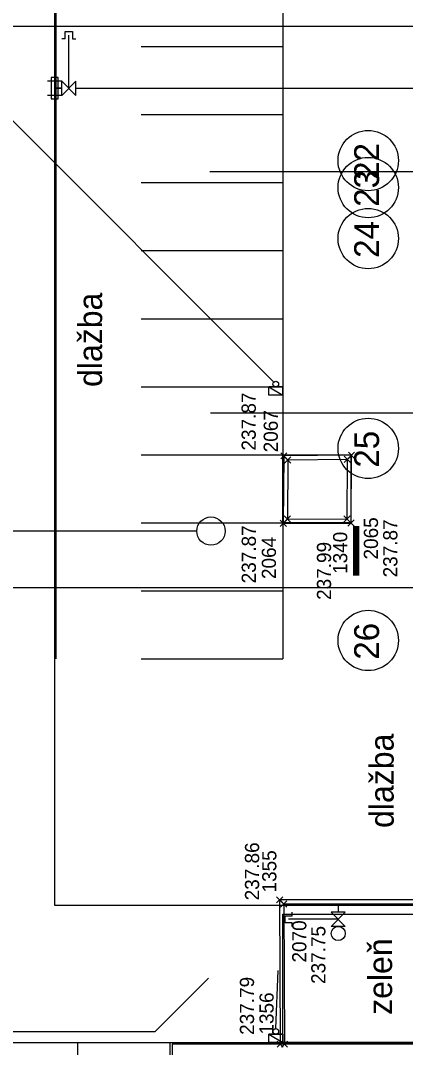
# Model space of a CAD drawing. Extents: x -264205 to -263659, y -1242401 to -1241986.
# Drawn here: x -263925.35 to -263911.77, y -1242255.16 to -1242218.94 of the extents above; entities that cross this region are included whole.
import ezdxf

# ---------------------------------------------------------------- set-up
doc = ezdxf.new("R2010")
doc.units = 0
for name, color, linetype in [('BOD_CISLO_2-3', 7, 'Continuous'), ('BOD_SYMBOL_2-3', 7, 'Continuous'), ('BOD_VYSKA_2-3', 7, 'Continuous'), ('HESCON_OSI_STAVBY_KFA', 7, 'Continuous'), ('POPIS_2-3', 7, 'Continuous'), ('PROJEKT_OBRUBNIKY_KOMUNIKACIE', 7, 'Continuous'), ('PROJEKT_TDZ_VODOROVNE', 7, 'Continuous'), ('RAM_NA_TLAC_2-1_1-250', 7, 'Continuous'), ('SITUACIA_DSP_2D', 7, 'Continuous'), ('SO_20-2_OBRUBNIKY_DOLNA_HRANA', 7, 'Continuous'), ('SO_20-2_OBRUBNIKY_HORNA_HRANA', 7, 'Continuous'), ('SO_20-4_OBRUBNIKY_DOLNA_HRANA', 7, 'Continuous'), ('SO_20-4_OBRUBNIKY_HORNA_HRANA', 7, 'Continuous')]:
    doc.layers.add(name, color=color, linetype=linetype)

msp = doc.modelspace()

# ---------------------------------------------------------------- linework, layer by layer
at = {"layer": 'BOD_SYMBOL_2-3'}
for p, q in [((-263915.95, -1242234.406), (-263916.171, -1242234.184)), ((-263915.95, -1242234.184), (-263916.171, -1242234.406)), ((-263915.812, -1242234.552), (-263916.033, -1242234.332)), ((-263915.812, -1242234.332), (-263916.033, -1242234.552)), ((-263913.709, -1242234.532), (-263913.931, -1242234.311)), ((-263913.709, -1242234.311), (-263913.931, -1242234.532)), ((-263913.563, -1242234.383), (-263913.785, -1242234.161)), ((-263913.563, -1242234.161), (-263913.785, -1242234.383)), ((-263915.971, -1242236.782), (-263916.193, -1242236.561)), ((-263915.971, -1242236.561), (-263916.193, -1242236.782)), ((-263915.824, -1242236.636), (-263916.046, -1242236.414)), ((-263915.824, -1242236.414), (-263916.046, -1242236.636)), ((-263913.72, -1242236.629), (-263913.941, -1242236.407)), ((-263913.72, -1242236.407), (-263913.941, -1242236.629)), ((-263913.579, -1242236.775), (-263913.8, -1242236.555)), ((-263913.579, -1242236.555), (-263913.8, -1242236.775)), ((-263916.098, -1242250.065), (-263916.318, -1242249.843)), ((-263916.098, -1242249.843), (-263916.318, -1242250.065)), ((-263915.953, -1242250.214), (-263916.174, -1242249.992)), ((-263915.953, -1242249.992), (-263916.174, -1242250.214)), ((-263916.079, -1242255.154), (-263916.301, -1242254.933)), ((-263916.079, -1242254.933), (-263916.301, -1242255.154)), ((-263915.927, -1242255.154), (-263916.148, -1242254.933)), ((-263915.927, -1242254.933), (-263916.148, -1242255.154))]:
    msp.add_line(p, q, dxfattribs=at)
at = {"layer": 'HESCON_OSI_STAVBY_KFA'}
for centre in [(-263913.085, -1242223.882), (-263913.085, -1242224.832), (-263913.085, -1242226.632), (-263913.085, -1242234.032), (-263913.085, -1242240.807)]:
    msp.add_circle(centre, 1.064, dxfattribs=at)
at = {"layer": 'PROJEKT_OBRUBNIKY_KOMUNIKACIE'}
for p, q in [((-263916.093, -1242234.257), (-263913.693, -1242234.257)), ((-263916.093, -1242236.657), (-263916.093, -1242234.257)), ((-263913.693, -1242234.257), (-263913.693, -1242236.657)), ((-263913.693, -1242236.657), (-263916.093, -1242236.657)), ((-263916.093, -1242254.982), (-263916.093, -1242250.458)), ((-263916.093, -1242250.458), (-263909.043, -1242250.458)), ((-263929.58, -1242254.982), (-263920.08, -1242254.982)), ((-263920.08, -1242254.982), (-263920.08, -1242267.983)), ((-263920.08, -1242254.982), (-263901.868, -1242254.982)), ((-263909.043, -1242254.982), (-263916.093, -1242254.982))]:
    msp.add_line(p, q, dxfattribs=at)
at = {"layer": 'PROJEKT_TDZ_VODOROVNE'}
for p, q in [((-263924.088, -1242241.458), (-263924.093, -1242087.307)), ((-263916.093, -1242187.557), (-263916.093, -1242241.458)), ((-263921.093, -1242219.857), (-263916.093, -1242219.857)), ((-263921.093, -1242222.257), (-263916.093, -1242222.257)), ((-263921.093, -1242224.657), (-263916.093, -1242224.657)), ((-263921.093, -1242227.057), (-263916.093, -1242227.057)), ((-263921.093, -1242229.457), (-263916.093, -1242229.457)), ((-263921.093, -1242231.857), (-263916.093, -1242231.857)), ((-263921.093, -1242234.257), (-263916.093, -1242234.257)), ((-263921.093, -1242236.657), (-263916.093, -1242236.657)), ((-263921.093, -1242239.057), (-263916.093, -1242239.057)), ((-263921.093, -1242241.458), (-263916.093, -1242241.458)), ((-263923.33, -1242296.482), (-263923.33, -1242254.982))]:
    msp.add_line(p, q, dxfattribs=at)
at = {"layer": 'RAM_NA_TLAC_2-1_1-250'}
msp.add_lwpolyline([(-264147.913, -1242144.907), (-263857.913, -1242144.907), (-263857.913, -1242219.157), (-264147.913, -1242219.157)], close=True, dxfattribs=at)
at = {"layer": 'SITUACIA_DSP_2D'}
for p, q in [((-263924.143, -1242185.14), (-263924.143, -1242250.14)), ((-263923.768, -1242219.582), (-263923.893, -1242219.582)), ((-263923.768, -1242219.582), (-263923.768, -1242219.332)), ((-263923.768, -1242219.332), (-263923.518, -1242219.332)), ((-263923.643, -1242221.332), (-263923.643, -1242219.457)), ((-263923.518, -1242219.332), (-263923.518, -1242219.582)), ((-263923.518, -1242219.582), (-263923.393, -1242219.582)), ((-263924.018, -1242220.957), (-263924.268, -1242220.957)), ((-263924.268, -1242220.957), (-263924.268, -1242221.707)), ((-263924.018, -1242221.707), (-263924.018, -1242220.957)), ((-263923.893, -1242221.082), (-263924.393, -1242221.082)), ((-263924.143, -1242221.332), (-263923.893, -1242221.332)), ((-263923.893, -1242221.332), (-263924.143, -1242221.332)), ((-263923.893, -1242221.582), (-263923.893, -1242221.082)), ((-263923.893, -1242221.082), (-263923.393, -1242221.582)), ((-263923.393, -1242221.082), (-263923.893, -1242221.582)), ((-263923.393, -1242221.582), (-263923.393, -1242221.082)), ((-263923.393, -1242221.332), (-263903.343, -1242221.332)), ((-263923.893, -1242221.582), (-263924.393, -1242221.582)), ((-263924.268, -1242221.707), (-263924.018, -1242221.707)), ((-263916.414, -1242231.691), (-263926.24, -1242221.865)), ((-263908.718, -1242224.282), (-263918.67, -1242224.282)), ((-263916.593, -1242231.862), (-263916.093, -1242231.862)), ((-263916.593, -1242232.152), (-263916.593, -1242231.862)), ((-263916.593, -1242231.862), (-263916.093, -1242232.152)), ((-263916.593, -1242231.862), (-263916.093, -1242232.152)), ((-263916.093, -1242231.862), (-263916.593, -1242231.862)), ((-263916.093, -1242231.862), (-263916.093, -1242232.152)), ((-263916.093, -1242232.152), (-263916.093, -1242231.862)), ((-263916.093, -1242232.152), (-263916.593, -1242232.152)), ((-263905.894, -1242232.793), (-263918.643, -1242232.793)), ((-263916.093, -1242234.257), (-263913.693, -1242234.257)), ((-263916.093, -1242236.657), (-263916.093, -1242234.257)), ((-263913.693, -1242234.257), (-263913.693, -1242236.657)), ((-263919.13, -1242236.949), (-263926.43, -1242236.949)), ((-263913.693, -1242236.657), (-263916.093, -1242236.657)), ((-263907.219, -1242238.949), (-263926.43, -1242238.949)), ((-263924.143, -1242250.14), (-263788.143, -1242250.14)), ((-263915.768, -1242250.515), (-263915.768, -1242250.39)), ((-263914.393, -1242250.39), (-263913.893, -1242250.89)), ((-263913.893, -1242250.39), (-263914.393, -1242250.39)), ((-263914.393, -1242250.89), (-263913.893, -1242250.39)), ((-263914.143, -1242250.14), (-263914.143, -1242250.39)), ((-263914.143, -1242250.14), (-263914.143, -1242250.39)), ((-263916.093, -1242254.982), (-263916.093, -1242250.458)), ((-263916.093, -1242250.458), (-263909.043, -1242250.458)), ((-263916.018, -1242250.515), (-263915.768, -1242250.515)), ((-263916.018, -1242250.765), (-263916.018, -1242250.515)), ((-263915.768, -1242250.765), (-263916.018, -1242250.765)), ((-263914.143, -1242250.64), (-263915.893, -1242250.64)), ((-263915.768, -1242250.89), (-263915.768, -1242250.765)), ((-263913.893, -1242250.89), (-263914.393, -1242250.89)), ((-263916.339, -1242254.492), (-263916.265, -1242252.443)), ((-263920.595, -1242254.592), (-263918.723, -1242252.72)), ((-263929.73, -1242254.592), (-263920.595, -1242254.592)), ((-263916.593, -1242254.692), (-263916.093, -1242254.692)), ((-263916.593, -1242254.982), (-263916.593, -1242254.692)), ((-263916.593, -1242254.692), (-263916.093, -1242254.982)), ((-263916.593, -1242254.692), (-263916.093, -1242254.982)), ((-263916.093, -1242254.692), (-263916.593, -1242254.692)), ((-263916.093, -1242254.692), (-263916.093, -1242254.982)), ((-263916.093, -1242254.982), (-263916.093, -1242254.692)), ((-263916.093, -1242254.982), (-263916.593, -1242254.982)), ((-263909.043, -1242254.982), (-263916.093, -1242254.982))]:
    msp.add_line(p, q, dxfattribs=at)
for centre, radius in [((-263916.343, -1242231.762), 0.1), ((-263918.63, -1242236.949), 0.5), ((-263914.143, -1242251.14), 0.25), ((-263916.343, -1242254.592), 0.1)]:
    msp.add_circle(centre, radius, dxfattribs=at)
at = {"layer": 'SO_20-2_OBRUBNIKY_DOLNA_HRANA'}
msp.add_line((-263920.002, -1242255.04), (-263920, -1242263.92), dxfattribs=at)
at = {"layer": 'SO_20-2_OBRUBNIKY_HORNA_HRANA'}
msp.add_lwpolyline([(-263854.465, -1242263.815), (-263854.458, -1242255.02), (-263866.883, -1242255.042), (-263883.752, -1242255.044), (-263902.029, -1242255.047), (-263909.175, -1242255.048), (-263919.956, -1242255.04), (-263920.002, -1242255.04)], dxfattribs=at)
at = {"layer": 'SO_20-4_OBRUBNIKY_DOLNA_HRANA'}
msp.add_line((-263916.061, -1242234.295), (-263916.082, -1242236.671), dxfattribs=at)
for points in [[(-263916.082, -1242236.671), (-263913.689, -1242236.665), (-263913.674, -1242234.272), (-263916.061, -1242234.295)], [(-263909.325, -1242255.048), (-263909.371, -1242250.107), (-263916.063, -1242250.103), (-263916.037, -1242255.043)]]:
    msp.add_lwpolyline(points, dxfattribs=at)
at = {"layer": 'SO_20-4_OBRUBNIKY_HORNA_HRANA'}
msp.add_line((-263915.922, -1242234.442), (-263915.935, -1242236.525), dxfattribs=at)
for points in [[(-263915.935, -1242236.525), (-263913.83, -1242236.518), (-263913.82, -1242234.421), (-263915.922, -1242234.442)], [(-263909.222, -1242249.957), (-263916.208, -1242249.954), (-263916.19, -1242255.043)]]:
    msp.add_lwpolyline(points, dxfattribs=at)

# ---------------------------------------------------------------- texts
at = {"layer": 'BOD_CISLO_2-3'}
for s, p in [('2067', (-263916.272, -1242234.17)), ('2065', (-263912.74, -1242237.95)), ('1340', (-263913.824, -1242238.459)), ('2064', (-263916.338, -1242238.639)), ('1355', (-263916.324, -1242249.694)), ('2070', (-263915.266, -1242252.165)), ('1356', (-263916.42, -1242254.706))]:
    msp.add_text(s, height=0.5, rotation=90, dxfattribs=at).set_placement(p)
at = {"layer": 'BOD_VYSKA_2-3'}
for s, p in [('237.87', (-263917.051, -1242234.108)), ('237.87', (-263912.057, -1242238.582)), ('237.87', (-263917.047, -1242238.791)), ('237.99', (-263914.395, -1242239.375)), ('237.86', (-263916.932, -1242249.972)), ('237.75', (-263914.594, -1242252.921)), ('237.79', (-263917.111, -1242254.716))]:
    msp.add_text(s, height=0.5, rotation=90, dxfattribs=at).set_placement(p)
at = {"layer": 'HESCON_OSI_STAVBY_KFA'}
for s, p in [('22', (-263912.704, -1242224.562)), ('23', (-263912.704, -1242225.512)), ('24', (-263912.704, -1242227.312)), ('25', (-263912.704, -1242234.712)), ('26', (-263912.704, -1242241.487))]:
    msp.add_text(s, height=0.875, rotation=90, dxfattribs=at).set_placement(p)
at = {"layer": 'POPIS_2-3'}
for s, p in [('dlažba', (-263922.468, -1242231.865)), ('dlažba', (-263912.188, -1242247.418)), ('zeleň', (-263912.244, -1242254.011))]:
    msp.add_text(s, height=0.8438, rotation=90, dxfattribs=at).set_placement(p)
at = {"layer": 'SITUACIA_DSP_2D'}
msp.add_text('I', height=1.75, dxfattribs=at).set_placement((-263913.835, -1242238.519))

doc.saveas('drawing.dxf')
